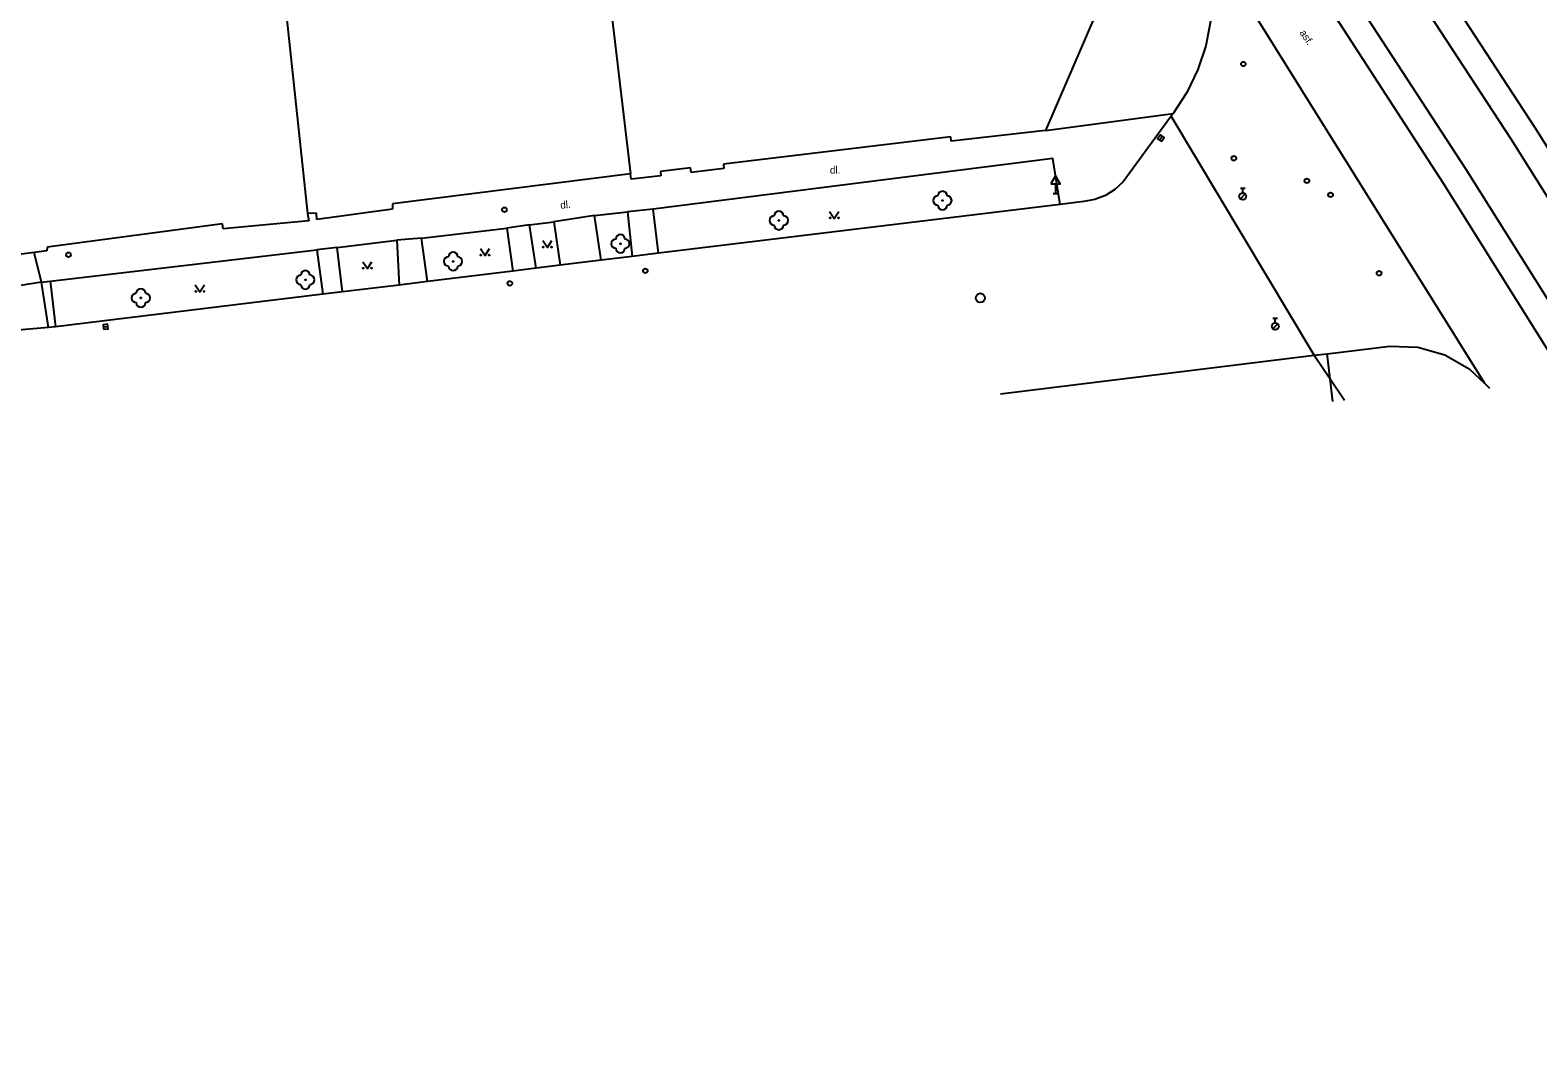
# Model space of a CAD drawing. Extents: x -599770 to -598493, y -1162076 to -1159209.
# Drawn here: x -598888.7 to -598807, y -1159880.5 to -1159825.4 of the extents above; entities that cross this region are included whole.
import ezdxf

# ---------------------------------------------------------------- set-up
doc = ezdxf.new("R2010")
doc.units = 0
doc.layers.add('Podklad', color=7, linetype='Continuous')

msp = doc.modelspace()

# ---------------------------------------------------------------- linework, layer by layer
at = {"layer": 'Podklad'}
for p, q in [((-598827.473, -1159831.331), (-598827.327, -1159831.129)), ((-598833.11, -1159833.711), (-598833.11, -1159834.22)), ((-598833.235, -1159834.22), (-598832.985, -1159834.22)), ((-598823.089, -1159834.516), (-598822.824, -1159834.251)), ((-598823.085, -1159833.942), (-598822.835, -1159833.942)), ((-598822.96, -1159834.192), (-598822.96, -1159833.942)), ((-598821.325, -1159840.992), (-598821.075, -1159840.992)), ((-598821.2, -1159841.242), (-598821.2, -1159840.992)), ((-598884.734, -1159841.463), (-598884.486, -1159841.437)), ((-598821.329, -1159841.566), (-598821.064, -1159841.301))]:
    msp.add_line(p, q, dxfattribs=at)
for points in [[(-598843.75, -1159776.99), (-598840.19, -1159781.92), (-598830.23, -1159795.83), (-598820.48, -1159810.31), (-598817.71, -1159814.42), (-598807.13, -1159830.65), (-598799.62, -1159842.54), (-598789.32, -1159859.23), (-598777.02, -1159879.05), (-598762.59, -1159902.44), (-598742.56, -1159934.87), (-598727.66, -1159958.93), (-598713.4, -1159981.9), (-598704.83, -1159995.51), (-598704.576, -1159995.888), (-598697.85, -1160005.91), (-598688.24, -1160019.21)], [(-598778.11, -1159879.76), (-598782.03, -1159873.55), (-598790.61, -1159859.97), (-598800.87, -1159843.29), (-598808.4, -1159831.29), (-598818.91, -1159815.22), (-598831.24, -1159796.87), (-598839.97, -1159784.58), (-598844.33, -1159778.48)], [(-598847.33, -1159779.54), (-598842.36, -1159786.4), (-598833.69, -1159798.5), (-598821.25, -1159816.96), (-598810.86, -1159832.91), (-598803.35, -1159844.88), (-598793.06, -1159861.51), (-598780.64, -1159881.42)], [(-598848.47, -1159780.35), (-598842.79, -1159788.17), (-598834.87, -1159799.27), (-598822.51, -1159817.59), (-598812.1, -1159833.66), (-598794.85, -1159861.18), (-598781.86, -1159882.23), (-598733.11, -1159961.13)], [(-598825.43, -1159819.52), (-598824.99, -1159820.81), (-598824.72, -1159822.15), (-598824.63, -1159823.51), (-598824.71, -1159824.88), (-598824.97, -1159826.22), (-598825.4, -1159827.51), (-598825.99, -1159828.75), (-598826.73, -1159829.89)], [(-598809.84, -1159844.53), (-598825.43, -1159819.52)], [(-598857.66, -1159820.49), (-598856.15, -1159833.17)], [(-598875.1, -1159821.91), (-598873.66, -1159835.32)], [(-598830.69, -1159823.95), (-598833.65, -1159830.81)], [(-598833.65, -1159830.81), (-598826.73, -1159829.89)], [(-598826.73, -1159829.89), (-598826.84, -1159830.04), (-598829.45, -1159833.6)], [(-598819.09, -1159843), (-598826.84, -1159830.04)], [(-598838.79, -1159831.15), (-598851.12, -1159832.63)], [(-598838.76, -1159831.4), (-598838.79, -1159831.15)], [(-598833.65, -1159830.81), (-598838.76, -1159831.4)], [(-598832.86, -1159834.82), (-598833.25, -1159832.33), (-598854.93, -1159835.07)], [(-598852.9, -1159832.84), (-598854.53, -1159833.03)], [(-598854.53, -1159833.03), (-598854.5, -1159833.27)], [(-598852.87, -1159833.09), (-598852.9, -1159832.84)], [(-598851.09, -1159832.88), (-598852.87, -1159833.09)], [(-598851.12, -1159832.63), (-598851.09, -1159832.88)], [(-598856.15, -1159833.17), (-598869.06, -1159834.79)], [(-598856.12, -1159833.46), (-598856.15, -1159833.17)], [(-598854.5, -1159833.27), (-598856.12, -1159833.46)], [(-598829.45, -1159833.6), (-598829.9, -1159834.01), (-598830.41, -1159834.33), (-598830.98, -1159834.55), (-598831.57, -1159834.66)], [(-598831.57, -1159834.66), (-598832.86, -1159834.82)], [(-598873.17, -1159835.3), (-598873.66, -1159835.32)], [(-598873.66, -1159835.32), (-598873.6, -1159835.71)], [(-598873.15, -1159835.63), (-598873.17, -1159835.3)], [(-598869.05, -1159835.08), (-598873.15, -1159835.63)], [(-598869.06, -1159834.79), (-598869.05, -1159835.08)], [(-598858.11, -1159835.43), (-598860.31, -1159835.77)], [(-598857.74, -1159837.85), (-598858.11, -1159835.43), (-598856.32, -1159835.23), (-598856.07, -1159837.65)], [(-598854.93, -1159835.07), (-598856.32, -1159835.23)], [(-598854.64, -1159837.47), (-598854.93, -1159835.07)], [(-598832.86, -1159834.82), (-598854.64, -1159837.47)], [(-598845.36, -1159835.205), (-598845.11, -1159835.58), (-598844.86, -1159835.205)], [(-598878.28, -1159835.88), (-598887.78, -1159837.13)], [(-598878.24, -1159836.15), (-598878.28, -1159835.88)], [(-598873.6, -1159835.71), (-598878.24, -1159836.15)], [(-598867.16, -1159839), (-598867.49, -1159836.65), (-598862.86, -1159836.1), (-598862.54, -1159838.44)], [(-598861.62, -1159835.92), (-598862.86, -1159836.1)], [(-598861.26, -1159838.28), (-598861.62, -1159835.92), (-598860.31, -1159835.77), (-598859.97, -1159838.12)], [(-598887.78, -1159837.13), (-598887.8, -1159837.33)], [(-598871.77, -1159839.56), (-598872.06, -1159837.15), (-598868.82, -1159836.76), (-598868.7, -1159839.19)], [(-598867.49, -1159836.65), (-598868.82, -1159836.76)], [(-598860.91, -1159836.785), (-598860.66, -1159837.16), (-598860.41, -1159836.785)], [(-598888.48, -1159837.42), (-598891.25, -1159837.79)], [(-598887.8, -1159837.33), (-598888.48, -1159837.42)], [(-598888.09, -1159839.03), (-598888.48, -1159837.42)], [(-598888.09, -1159839.03), (-598887.62, -1159838.98), (-598873.15, -1159837.28), (-598872.84, -1159839.69)], [(-598872.06, -1159837.15), (-598873.15, -1159837.28)], [(-598870.67, -1159837.925), (-598870.42, -1159838.3), (-598870.17, -1159837.925)], [(-598864.29, -1159837.215), (-598864.04, -1159837.59), (-598863.79, -1159837.215)], [(-598857.74, -1159837.85), (-598859.97, -1159838.12)], [(-598856.07, -1159837.65), (-598857.74, -1159837.85)], [(-598854.64, -1159837.47), (-598856.07, -1159837.65)], [(-598862.54, -1159838.44), (-598867.16, -1159839)], [(-598861.26, -1159838.28), (-598862.54, -1159838.44)], [(-598859.97, -1159838.12), (-598861.26, -1159838.28)], [(-598888.09, -1159839.03), (-598891.04, -1159839.5)], [(-598887.71, -1159841.5), (-598888.09, -1159839.03)], [(-598887.62, -1159838.98), (-598887.605, -1159839.127), (-598887.32, -1159841.45)], [(-598879.75, -1159839.185), (-598879.5, -1159839.56), (-598879.25, -1159839.185)], [(-598871.77, -1159839.56), (-598872.84, -1159839.69)], [(-598868.7, -1159839.19), (-598871.77, -1159839.56)], [(-598867.16, -1159839), (-598868.7, -1159839.19)], [(-598872.84, -1159839.69), (-598887.32, -1159841.45), (-598887.71, -1159841.5)], [(-598887.71, -1159841.5), (-598891.03, -1159841.78)], [(-598819.09, -1159843), (-598818.39, -1159842.92), (-598814.98, -1159842.5)], [(-598814.98, -1159842.5), (-598813.46, -1159842.55), (-598812, -1159842.97), (-598810.68, -1159843.73), (-598809.84, -1159844.53), (-598809.58, -1159844.78)], [(-598836.09, -1159845.09), (-598819.09, -1159843)], [(-598819.09, -1159843), (-598818.229, -1159844.269), (-598817.44, -1159845.43)], [(-598818.08, -1159845.51), (-598818.229, -1159844.269), (-598818.39, -1159842.92)]]:
    msp.add_lwpolyline(points, dxfattribs=at)
for points in [[(-598827.372, -1159831.404), (-598827.226, -1159831.202), (-598827.428, -1159831.056), (-598827.574, -1159831.258)], [(-598833.36, -1159833.711), (-598832.86, -1159833.711), (-598833.11, -1159833.278)], [(-598884.721, -1159841.587), (-598884.473, -1159841.561), (-598884.499, -1159841.313), (-598884.747, -1159841.339)]]:
    msp.add_lwpolyline(points, close=True, dxfattribs=at)
for centre, radius in [((-598822.93, -1159827.21), 0.125), ((-598823.44, -1159832.32), 0.125), ((-598819.48, -1159833.54), 0.125), ((-598839.24, -1159834.61), 0.025), ((-598822.96, -1159834.38), 0.188), ((-598818.2, -1159834.3), 0.125), ((-598862.99, -1159835.11), 0.125), ((-598848.11, -1159835.69), 0.025), ((-598845.335, -1159835.555), 0.025), ((-598844.885, -1159835.555), 0.025), ((-598860.885, -1159837.135), 0.025), ((-598860.435, -1159837.135), 0.025), ((-598856.7, -1159836.95), 0.025), ((-598886.62, -1159837.55), 0.125), ((-598865.77, -1159837.91), 0.025), ((-598864.265, -1159837.565), 0.025), ((-598863.815, -1159837.565), 0.025), ((-598870.645, -1159838.275), 0.025), ((-598870.195, -1159838.275), 0.025), ((-598855.35, -1159838.42), 0.125), ((-598815.57, -1159838.55), 0.125), ((-598879.725, -1159839.535), 0.025), ((-598879.275, -1159839.535), 0.025), ((-598873.78, -1159838.91), 0.025), ((-598862.69, -1159839.1), 0.125), ((-598882.7, -1159839.89), 0.025), ((-598837.19, -1159839.89), 0.25), ((-598821.2, -1159841.43), 0.188)]:
    msp.add_circle(centre, radius, dxfattribs=at)
for centre, start, end in [((-598839.49, -1159834.61), 90, 270), ((-598839.24, -1159834.36), 0, 180), ((-598838.99, -1159834.61), 270, 90), ((-598848.36, -1159835.69), 90, 270), ((-598848.11, -1159835.44), 0, 180), ((-598847.86, -1159835.69), 270, 90), ((-598839.24, -1159834.86), 180, 0), ((-598848.11, -1159835.94), 180, 0), ((-598856.95, -1159836.95), 90, 270), ((-598856.7, -1159836.7), 0, 180), ((-598856.45, -1159836.95), 270, 90), ((-598866.02, -1159837.91), 90, 270), ((-598865.77, -1159837.66), 0, 180), ((-598865.52, -1159837.91), 270, 90), ((-598856.7, -1159837.2), 180, 0), ((-598874.03, -1159838.91), 90, 270), ((-598873.78, -1159838.66), 0, 180), ((-598873.53, -1159838.91), 270, 90), ((-598865.77, -1159838.16), 180, 0), ((-598882.7, -1159839.64), 0, 180), ((-598873.78, -1159839.16), 180, 0), ((-598882.95, -1159839.89), 90, 270), ((-598882.7, -1159840.14), 180, 0), ((-598882.45, -1159839.89), 270, 90)]:
    msp.add_arc(centre, 0.25, start, end, dxfattribs=at)

# ---------------------------------------------------------------- texts
for s, rotation, p in [('asf.', 303.1, (-598819.9, -1159825.51)), ('dl.', 5.82, (-598859.94, -1159835.06))]:
    msp.add_text(s, height=0.4, rotation=rotation, dxfattribs=at).set_placement(p)
msp.add_text('dl.', height=0.4, dxfattribs=at).set_placement((-598845.34, -1159833.15))

doc.saveas('drawing.dxf')
